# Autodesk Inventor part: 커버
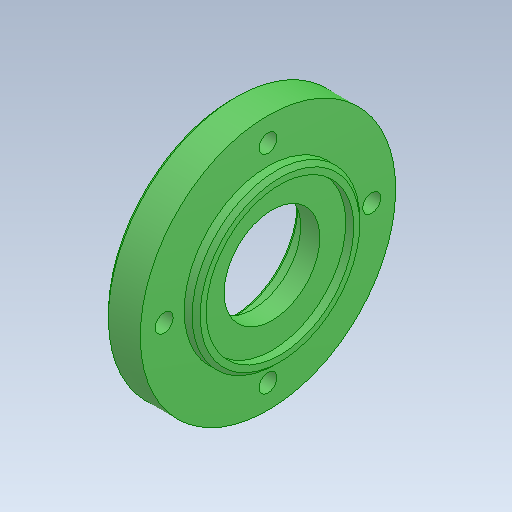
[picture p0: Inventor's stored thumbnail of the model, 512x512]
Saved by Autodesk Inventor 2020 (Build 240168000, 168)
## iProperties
Created: 2024-04
Part Number: 커버
Material: 알루미늄 6061
Document SubType Name: Modeling
Designer: oem
Density: 2.71 g/cm^3
Appearance: 기본값
Mass: 63.0244 g
Surface Area: 92.0832 cm^2
Volume: 23.2562 cm^3
Sending System: Autodesk Inventor 2025
Preprocessor: ST-DEVELOPER v20
Author: jhkim
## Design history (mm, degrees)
feature "솔리드1"
node "솔리드2"
